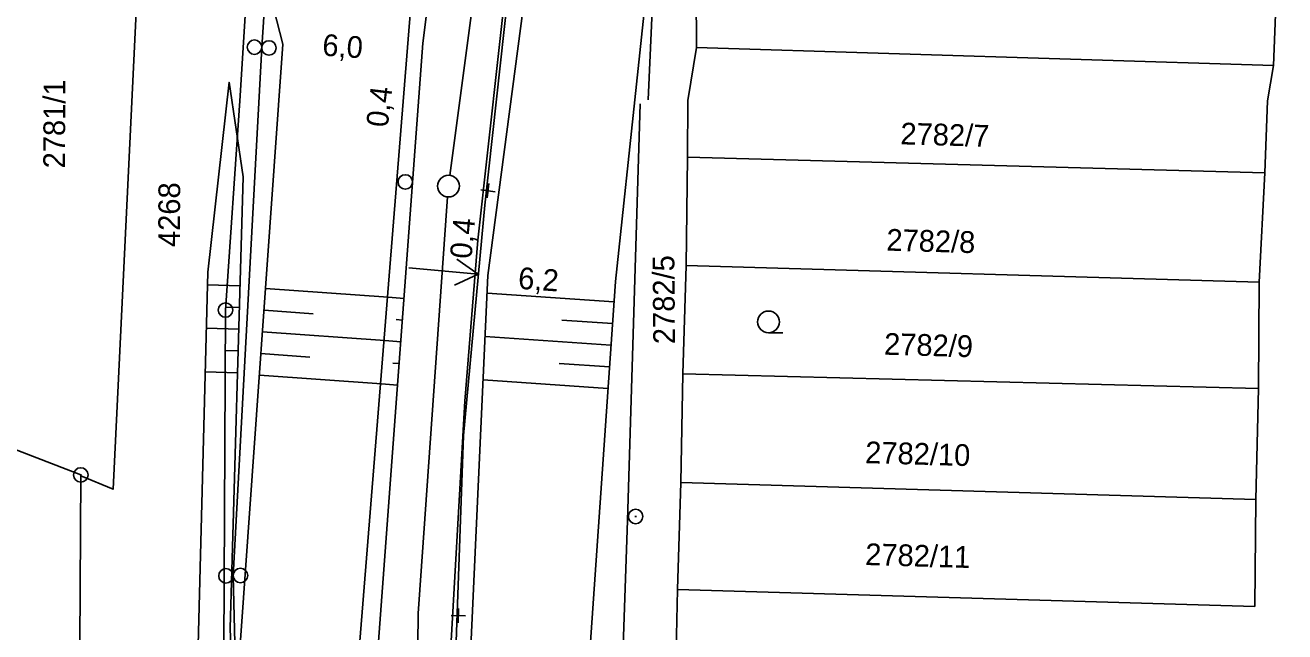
# Model space of a CAD drawing. Extents: x -658910 to -658078, y -1170373 to -1169331.
# Drawn here: x -658449.7 to -658362.8, y -1170036.9 to -1169995.1 of the extents above; entities that cross this region are included whole.
import ezdxf

# ---------------------------------------------------------------- set-up
doc = ezdxf.new("R2010")
doc.units = 0
for name, color, linetype in [('Vrstva 1', 7, 'Continuous'), ('Vrstva 10', 7, 'Continuous'), ('Vrstva 11', 7, 'Continuous'), ('Vrstva 12', 7, 'Continuous'), ('Vrstva 14', 7, 'Continuous'), ('Vrstva 26', 7, 'Continuous'), ('Vrstva 6', 7, 'Continuous'), ('Vrstva 8', 7, 'Continuous'), ('Vrstva 9', 7, 'Continuous')]:
    doc.layers.add(name, color=color, linetype=linetype)

msp = doc.modelspace()

# ---------------------------------------------------------------- linework, layer by layer
at = {"layer": 'Vrstva 1'}
for p, q in [((-658435.96, -1170014.719), (-658435.86, -1170014.719)), ((-658407.652, -1170028.961), (-658407.552, -1170028.961))]:
    msp.add_line(p, q, dxfattribs=at)
for points in [[(-658434.91, -1170000.301), (-658433.32, -1169974.6), (-658432.57, -1169965.9), (-658431.148, -1169951.469), (-658415.48, -1169909.85), (-658422.289, -1169902.77), (-658428.09, -1169905.961)], [(-658406.031, -1169984.301), (-658406.73, -1170000.219)], [(-658403.5, -1170214.23), (-658416.398, -1170174.469), (-658429.102, -1170126.129), (-658434.469, -1170087.609), (-658436.09, -1170052.059), (-658435.91, -1170014.719), (-658434.91, -1170000.301)], [(-658407.281, -1170000.499), (-658408.153, -1170029.241), (-658409.34, -1170063.27), (-658409.781, -1170095.35), (-658409.699, -1170099.11), (-658407.621, -1170136.909), (-658406.442, -1170153.331), (-658402.571, -1170171.88), (-658370.821, -1170208.971)]]:
    msp.add_lwpolyline(points, dxfattribs=at)
for centre in [(-658435.91, -1170014.719), (-658407.602, -1170028.961)]:
    msp.add_circle(centre, 0.499, dxfattribs=at)
at = {"layer": 'Vrstva 10'}
msp.add_line((-658419.943, -1170011.204), (-658418.472, -1170012.243), dxfattribs=at)
for points in [[(-658398.979, -1170189.297), (-658404.442, -1170166.563), (-658409.088, -1170142.051), (-658411.131, -1170114.565), (-658412.045, -1170080.658), (-658411.524, -1170049.223), (-658409, -1170012.742), (-658406.097, -1169985.499), (-658398.397, -1169958.238), (-658397.23, -1169955.206)], [(-658418.194, -1170104.631), (-658419.779, -1170081.152), (-658420.352, -1170064.135), (-658420.207, -1170044.041), (-658419.481, -1170023.386), (-658418.014, -1170007.481), (-658415.888, -1169988.253), (-658413.097, -1169969.872), (-658411.043, -1169959.49)], [(-658417.872, -1169961.611), (-658420.49, -1169976.06), (-658420.7, -1169976.84), (-658423.094, -1169993.471), (-658426.642, -1170037.568), (-658427.061, -1170074.546), (-658424.838, -1170104.223), (-658420.758, -1170135.42), (-658415.909, -1170162.863), (-658409.329, -1170190.564)], [(-658402.315, -1170190.348), (-658407.653, -1170169.771), (-658412.172, -1170148.826), (-658415.215, -1170129.375), (-658417.727, -1170109.679), (-658419.363, -1170090.792), (-658420.432, -1170070.237), (-658420.644, -1170050.611), (-658420.516, -1170040.788), (-658419.395, -1170021.018), (-658418.485, -1170009.912), (-658416.352, -1169990.562), (-658415.125, -1169981.811), (-658411.561, -1169961.716)], [(-658411.065, -1170191.125), (-658419.009, -1170162.093), (-658425.437, -1170135.194), (-658430.311, -1170105.886), (-658434.217, -1170075.522), (-658434.962, -1170038.771), (-658431.942, -1169996.387), (-658433.406, -1169990.734), (-658432.798, -1169972.528), (-658431.022, -1169965.688)], [(-658408.116, -1170190.76), (-658414.795, -1170162.084), (-658419.971, -1170133.751), (-658423.753, -1170102.123), (-658425.468, -1170076.574), (-658425.385, -1170038.217), (-658422.281, -1169996.311), (-658419.933, -1169977.592), (-658415.95, -1169967.863)], [(-658411.797, -1169969.902), (-658412.351, -1169971.115), (-658417.802, -1170012.345), (-658419.546, -1170050.542), (-658418.979, -1170083.49), (-658416.97, -1170109.116)], [(-658434.217, -1170075.522), (-658435.579, -1170036.672), (-658434.69, -1170005.528), (-658435.667, -1169999.009), (-658437.119, -1170012.108), (-658437.881, -1170041.388), (-658436.997, -1170074.409), (-658433.517, -1170107.658), (-658428.206, -1170138.963), (-658421.128, -1170167.236), (-658412.684, -1170191.854)], [(-658423.252, -1170011.803), (-658418.472, -1170012.243), (-658420.108, -1170012.996)], [(-658434.905, -1170013.048), (-658437.142, -1170012.984)], [(-658433.143, -1170013.236), (-658424.672, -1170013.839)], [(-658409.098, -1170014.157), (-658417.857, -1170013.551)], [(-658423.585, -1170013.92), (-658424.672, -1170013.839)], [(-658434.948, -1170014.548), (-658435.841, -1170014.522)], [(-658433.249, -1170014.732), (-658429.866, -1170014.973)], [(-658434.99, -1170016.047), (-658437.22, -1170015.983)], [(-658423.696, -1170015.416), (-658424.135, -1170015.383)], [(-658409.202, -1170015.654), (-658412.691, -1170015.412)], [(-658433.356, -1170016.228), (-658424.913, -1170016.83)], [(-658423.807, -1170016.912), (-658424.913, -1170016.83)], [(-658409.305, -1170017.15), (-658417.994, -1170016.549)], [(-658435.033, -1170017.546), (-658435.924, -1170017.521)], [(-658433.462, -1170017.724), (-658430.091, -1170017.964)], [(-658423.917, -1170018.408), (-658424.364, -1170018.375)], [(-658409.409, -1170018.646), (-658412.87, -1170018.407)], [(-658435.076, -1170019.046), (-658437.298, -1170018.982)], [(-658433.569, -1170019.221), (-658425.153, -1170019.82)], [(-658409.512, -1170020.143), (-658418.131, -1170019.547)], [(-658424.028, -1170019.904), (-658425.153, -1170019.82)]]:
    msp.add_lwpolyline(points, dxfattribs=at)
at = {"layer": 'Vrstva 12'}
for p, q in [((-658418.284, -1170006.431), (-658417.293, -1170006.56)), ((-658417.853, -1170006.991), (-658417.724, -1170006)), ((-658419.841, -1170036.306), (-658419.83, -1170035.307)), ((-658420.335, -1170035.801), (-658419.336, -1170035.812))]:
    msp.add_line(p, q, dxfattribs=at)
at = {"layer": 'Vrstva 14'}
msp.add_circle((-658423.501, -1170005.886), 0.5, dxfattribs=at)
at = {"layer": 'Vrstva 26'}
msp.add_line((-658430.35, -1169951.67), (-658433.41, -1169996.588), dxfattribs=at)
msp.add_lwpolyline([(-658429.464, -1170116.165), (-658434.398, -1170073.025), (-658435.378, -1170033.046), (-658433.411, -1169996.615)], dxfattribs=at)
for centre in [(-658433.91, -1169996.588), (-658432.911, -1169996.641), (-658435.877, -1170033.058), (-658434.878, -1170033.033)]:
    msp.add_circle(centre, 0.5, dxfattribs=at)
at = {"layer": 'Vrstva 6'}
for points in [[(-658420.42, -1170005.444), (-658416.553, -1169976.435), (-658413.625, -1169960.291)], [(-658420.59, -1170105.878), (-658421.583, -1170095.123), (-658422.938, -1170065.589), (-658422.609, -1170035.66), (-658420.58, -1170006.923)]]:
    msp.add_lwpolyline(points, dxfattribs=at)
msp.add_circle((-658420.517, -1170006.172), 0.75, dxfattribs=at)
at = {"layer": 'Vrstva 8'}
msp.add_line((-658445.899, -1170026.149), (-658445.896, -1170026.05), dxfattribs=at)
msp.add_line((-658445.899, -1170026.149), (-658445.896, -1170026.05), dxfattribs=at)
for points in [[(-658445.899, -1170026.149), (-658443.671, -1170027.088), (-658441.279, -1169977.44)], [(-658356, -1170000.34), (-658355.25, -1169984.07), (-658362.988, -1169979.84), (-658363.012, -1169982.58), (-658363.27, -1169990.23), (-658363.57, -1169997.859), (-658363.98, -1170000.289)], [(-658404, -1170000.27), (-658403.398, -1169996.621), (-658403.449, -1169988.99), (-658403.34, -1169981.51), (-658405.129, -1169981.4)], [(-658403.398, -1169996.621), (-658363.57, -1169997.859)], [(-658404, -1170000.27), (-658404.031, -1170004.18), (-658404.121, -1170011.66), (-658404.34, -1170019.121), (-658404.48, -1170026.609), (-658404.719, -1170033.99), (-658404.891, -1170042.461), (-658405.078, -1170050.08), (-658405.129, -1170057.539), (-658405.301, -1170065.09), (-658405.57, -1170072.531), (-658405.719, -1170080.031), (-658405.84, -1170087.559), (-658406.129, -1170094.961), (-658374.988, -1170096.02), (-658366.531, -1170096.18), (-658366.32, -1170088.719), (-658366.148, -1170081.16), (-658365.91, -1170073.9), (-658365.801, -1170066.211), (-658365.422, -1170058.879), (-658365.371, -1170051.43), (-658365.148, -1170043.74), (-658404.891, -1170042.461)], [(-658404.719, -1170033.99), (-658364.871, -1170035.16), (-658364.781, -1170027.801), (-658364.602, -1170020.129), (-658364.559, -1170012.789), (-658364.16, -1170005.25), (-658363.98, -1170000.289)], [(-658404.031, -1170004.18), (-658364.16, -1170005.25)], [(-658468.641, -1170036.621), (-658499.16, -1170024.449), (-658492.879, -1170007.641), (-658459.801, -1170020.74), (-658445.898, -1170026.1)], [(-658364.559, -1170012.789), (-658404.121, -1170011.66)], [(-658364.602, -1170020.129), (-658404.34, -1170019.121)], [(-658445.898, -1170026.1), (-658445.898, -1170026.1), (-658446.02, -1170045.57), (-658445.059, -1170046.301), (-658440.281, -1170048.02), (-658438.469, -1170085.941), (-658475.52, -1170069.85), (-658484.629, -1170065.83), (-658477.73, -1170053.32), (-658468.641, -1170036.621), (-658446.02, -1170045.57)], [(-658364.781, -1170027.801), (-658404.48, -1170026.609)]]:
    msp.add_lwpolyline(points, dxfattribs=at)
msp.add_circle((-658445.898, -1170026.1), 0.499, dxfattribs=at)
msp.add_circle((-658445.898, -1170026.1), 0.499, dxfattribs=at)
at = {"layer": 'Vrstva 9'}
msp.add_line((-658398.43, -1170016.289), (-658397.43, -1170016.289), dxfattribs=at)
msp.add_circle((-658398.43, -1170015.539), 0.75, dxfattribs=at)

# ---------------------------------------------------------------- texts
at = {"layer": 'Vrstva 11'}
for s, rotation, p in [('6,0', 355.923, (-658429.263, -1169997.166)), ('0,4', 83.18885, (-658424.719, -1170002.163)), ('0,4', 84.73088, (-658418.932, -1170011.229)), ('6,2', 356.04294, (-658415.745, -1170013.252))]:
    msp.add_text(s, height=1.5, rotation=rotation, dxfattribs=at).set_placement(p)
at = {"layer": 'Vrstva 9'}
for s, rotation, p in [('2781/1', 89.7363, (-658446.99, -1170004.951)), ('2782/7', 358.35453, (-658389.34, -1170003.289)), ('4268', 89.7363, (-658439.056, -1170010.379)), ('2782/8', 358.35453, (-658390.309, -1170010.621)), ('2782/5', 90.44001, (-658404.883, -1170017.069)), ('2782/9', 358.35453, (-658390.469, -1170017.801)), ('2782/10', 358.35453, (-658391.77, -1170025.281)), ('2782/11', 358.35453, (-658391.77, -1170032.309))]:
    msp.add_text(s, height=1.5, rotation=rotation, dxfattribs=at).set_placement(p)

doc.saveas('drawing.dxf')
